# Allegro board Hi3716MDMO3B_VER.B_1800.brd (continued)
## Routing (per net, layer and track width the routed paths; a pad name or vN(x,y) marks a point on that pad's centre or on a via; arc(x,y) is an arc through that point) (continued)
VCC_SCI: length 16.9
  TOP w0.508: C193.1 R221.1 ; C193.1 257.34,82.94 256.73,82.33 J1.1 ; C193.1 C191.1 R130.2 258.71,86.65 C205.1 258.96,89.67 R274.2
VCC_SMT: length 11.8
  TOP w0.305: J26.1 221.66,50.95 220.67,51.94 J2.1 C223.1
VDD_AUDIO: length 19.1
  TOP w0.356: C75.1 208.67,129.07 209.18,128.56 U9.9
  TOP w0.381: v1(205.4,129.17) 205.51,129.06 R190.2 207.18,129.07 C75.1 ; C203.1 199.69,131.45 201.08,131.45 v1(203.36,129.17)
  TOP w0.508: C203.1 197.41,133.74 R151.2
  BOTTOM w0.381: v1(203.36,129.17) v1(205.4,129.17)
AUDIO_L: length 20.2
  TOP w0.254: R174.1 206.25,140.13 204.76,141.61 202.22,141.61 200.44,139.84 200.44,139.23 C216.1 197.24,136.69 196.12,137.8 196.12,139.43 J32.8
AUDIO_OUTL: length 28.1
  TOP w0.203: 205.07,101.81 204.45,102.43 U15.104
  TOP w0.254: 205.07,101.81 207.22,101.81 217.21,111.79 217.21,116.9 R152.1 C234.1
AUDIO_OUTR: length 26.2
  TOP w0.203: U15.105 204.76,102.83
  TOP w0.254: 204.76,102.83 206.74,102.83 215.94,112.02 215.94,116.96 R153.1 214.28,118.62 C235.2
AUDIO_R: length 4.6
  TOP w0.254: R175.2 C217.1 J32.7
CLK_50M_PHY0: length 90.7
  TOP w0.127: U3.9 103.45,115.74 102.78,115.07 102.78,109.86 105.9,106.74 134.19,106.74 138.78,111.34 177.89,111.34 178.85,110.37 179.33,110.37 C59.1 R162.2
CLK_50M_PHY1: length 79
  TOP w0.127: R163.2 C69.1 182.14,111.62 182.34,111.83 182.34,112.6 180.35,114.59 137.22,114.59 132.62,109.99 121.83,109.99 120.81,111.01 120.81,117.35 121.82,118.35 124.14,118.35 125.09,117.39 U4.9
CLK_SCI_NB: length 13.1
  TOP w0.305: J26.3 225.04,47.35 223.49,47.35 222.85,47.98 222.85,55.73 J2.2
CVBS: length 34.4
  TOP w0.203: U15.98 202.51,100.03 204.75,100.03
  TOP w0.254: 204.75,100.03 206.92,100.03 216.11,109.23 220.25,109.23 223.68,112.66 R34.2 R33.2 C70.1 223.68,117.74 224.21,118.26 U12.3
CVBS_OUT: length 21.3
  TOP w0.254: R65.1 220.03,131.58 216.7,131.58 214.79,133.49 C42.1 D3.3 J32.5
DATA_SCI_NB: length 46.7
  TOP w0.305: J26.7 230.67,14.88 J2.5
DDR_ADDR0: length 2.2
  TOP w0.127: U15.172 175.51,100.43 175.27,100.67 RN2.8
DDR_ADDR0_A: length 22.7
  TOP w0.127: U7.N3 160.81,91.03 160.81,91.61 160.53,91.89 160.23,91.89 159.98,92.13 159.98,93.49 160.18,93.68 160.18,96.91 164.6,101.33 172.57,101.33 173.23,100.67 RN2.1
DDR_ADDR1: length 5.8
  TOP w0.127: U15.17 185.42,76.81 R14.1
DDR_ADDR1_A: length 40.2
  TOP w0.127: U7.P7 159.9,87.94 158.22,87.94 156.55,86.27 156.55,81.67 163.76,74.46 173.57,74.46 174.46,73.57 182.18,73.57 R14.2
DDR_ADDR2: length 2.9
  TOP w0.127: R12.1 174.76,104.35 175.88,103.23 U15.165
DDR_ADDR2_A: length 32.2
  TOP w0.127: U7.P3 159.98,90.26 157.11,90.26 156.34,91.02 156.34,98.49 162.85,104.99 173.01,104.99 R12.2
DDR_ADDR3: length 2.2
  TOP w0.127: U15.173 175.35,100.03 175.22,100.16 RN2.7
DDR_ADDR3_A: length 19.8
  TOP w0.127: RN2.2 173.11,100.16 172.78,100.49 164.98,100.49 161.04,96.56 161.04,93.38 160.78,93.12 160.78,92.02 161.18,91.62 U7.N2
DDR_ADDR4: length 2.6
  TOP w0.127: RN5.8 182.62,78.64 U15.10
DDR_ADDR4_A: length 29.1
  TOP w0.127: U7.P8 159.98,86.26 159.98,84.9 159.77,84.69 159.77,82.44 164.86,77.35 174.79,77.35 175.68,76.46 180.44,76.46 RN5.1
DDR_ADDR5: length 2.4
  TOP w0.127: RN1.5 175.09,101.56 175.82,100.83 U15.171
DDR_ADDR5_A: length 22.7
  TOP w0.127: U7.P2 160.16,91.46 159.74,91.89 159.39,91.89 159.18,92.09 159.18,93.22 159.8,93.84 159.8,97.14 164.37,101.71 172.7,101.71 172.85,101.56 RN1.4
DDR_ADDR6: length 3.2
  TOP w0.127: RN5.7 183.17,78.47 183.17,79.52 183.42,79.77 U15.12
DDR_ADDR6_A: length 30.1
  TOP w0.127: U7.R8 159.18,86.26 159.18,82.49 164.7,76.97 174.64,76.97 175.52,76.08 180.78,76.08 RN5.2
DDR_ADDR7: length 2.5
  TOP w0.127: RN1.6 175.06,102.07 175.9,101.23 U15.170
DDR_ADDR7_A: length 24.2
  TOP w0.127: RN1.3 173.23,102.07 172.75,102.55 163.99,102.55 158.93,97.49 158.93,94.5 158.32,93.89 158.32,92.14 158.63,91.83 159.06,91.83 159.43,91.46 U7.R2
DDR_ADDR8: length 3.7
  TOP w0.127: RN5.6 183.68,78.26 183.68,79.26 184.22,79.8 U15.14
DDR_ADDR8_A: length 32.2
  TOP w0.127: RN5.3 180.99,75.57 180,75.57 179.67,75.24 175.12,75.24 174.23,76.13 164.36,76.13 158.21,82.28 158.21,86.09 U7.T8
DDR_ADDR9: length 2.4
  TOP w0.127: RN1.8 175.09,103.08 175.74,102.43 U15.167
DDR_ADDR9_A: length 27.6
  TOP w0.127: RN1.1 173.36,103.08 172.68,103.77 163.4,103.77 157.56,97.93 157.56,91.58 158.11,91.03 159.21,91.03 U7.R3
DDR_ADDR10: length 4
  TOP w0.127: U15.7 181.42,79.41 179.86,77.86 RN4.7
DDR_ADDR10_A: length 22.8
  TOP w0.127: RN4.2 177.46,77.86 175.89,79.42 165.73,79.42 162.41,82.75 162.41,87.09 U7.L7
DDR_ADDR11: length 4.1
  TOP w0.127: RN5.5 184.18,78.04 184.18,79 184.62,79.43 U15.15
DDR_ADDR11_A: length 34.8
  TOP w0.127: U7.R7 159.2,87.08 158.63,87.08 157.83,86.28 157.83,82.12 164.2,75.75 174.05,75.75 174.94,74.86 179.96,74.86 180.32,75.22 181.35,75.22 RN5.4
DDR_ADDR12: length 5.3
  TOP w0.127: U15.9 182.22,79.22 179.84,76.84 RN4.5
DDR_ADDR12_A: length 24.9
  TOP w0.127: RN4.4 176.67,76.84 175.32,78.19 165.21,78.19 160.78,82.62 160.78,87.06 U7.N7
DDR_ADDR13: length 5
  TOP w0.127: R13.1 172.78,104.35 173.49,103.64 175.01,103.64 175.82,102.83 U15.166
DDR_ADDR13_A: length 25.8
  TOP w0.127: U7.T3 157.92,90.66 157.18,91.4 157.18,98.1 163.23,104.15 171.53,104.15 R13.2
DDR_ADDR14: length 8.2
  TOP w0.127: U15.16 185.02,77.29 182.6,74.88 182.6,74.49 182.18,74.08 R15.1
DDR_ADDR14_A: length 33.9
  TOP w0.127: U7.T7 158.37,87.46 156.93,86.01 156.93,81.84 163.85,74.91 173.67,74.91 174.56,74.02 180.94,74.02 R15.2
DDR_BA0: length 2.5
  TOP w0.127: RN2.6 175.09,99.65 175.91,98.83 U15.176
DDR_BA0_A: length 19.1
  TOP w0.127: RN2.3 173.11,99.65 172.65,100.11 165.21,100.11 161.45,96.35 161.45,93.37 161.58,93.23 161.58,91.85 161.97,91.46 U7.M2
DDR_BA1: length 4.6
  TOP w0.127: U15.8 181.82,79.35 179.82,77.35 RN4.6
DDR_BA1_A: length 23.4
  TOP w0.127: RN4.3 176.69,77.35 175.47,78.57 165.36,78.57 161.4,82.53 161.4,84.67 161.58,84.85 161.58,86.26 U7.N8
DDR_BA2: length 2.4
  TOP w0.127: U15.177 175.78,98.43 175.06,99.15 RN2.5
DDR_BA2_A: length 18.4
  TOP w0.127: RN2.4 172.98,99.15 172.85,99.27 165.61,99.27 162.31,95.97 162.31,93.68 162.39,93.61 162.39,91.3 161.98,90.89 U7.M3
DDR_CASN: length 2.3
  TOP w0.127: U15.181 175.9,96.83 175.49,97.24 RN3.6
DDR_CASN_A: length 14.9
  TOP w0.127: U7.K3 163.58,90.85 164.01,91.27 164.01,92.46 164.4,92.85 164.4,94.96 166.66,97.22 173.34,97.22 173.36,97.24 RN3.3
DDR_CKE: length 5.1
  TOP w0.127: RN4.8 179.78,78.37 180.62,79.21 v1(180.62,79.26) 180.67,79.26 181.02,79.61 U15.6
  BOTTOM w0.127: v1(180.62,79.26) 181.26,79.26 181.64,79.64 R119.1
DDR_CKE_A: length 20.7
  TOP w0.127: RN4.1 177.51,78.37 176.07,79.8 165.88,79.8 162.8,82.89 162.8,85.08 U7.K9
DDR_CKN1: length 24.4
  TOP w0.165: U7.K7 163.58,87.22 163.98,86.82 163.98,85.52 164.25,85.25 164.25,83.55 R243.2 164.29,83.05 164.29,82.63 166.26,80.66 176.47,80.66 178.31,78.83 179.62,78.83 180.16,79.37 180.16,79.66 180.22,79.71 U15.4
DDR_CKP1: length 23.4
  TOP w0.165: U7.J7 164.38,87.4 164.79,86.99 164.79,85.52 164.54,85.27 164.54,83.61 R243.1 164.58,83.07 164.58,82.75 166.38,80.95 176.59,80.95 178.43,79.12 179.5,79.12 179.87,79.49 179.87,79.66 179.82,79.71 U15.3
DDR_CS0N_A: length 2.1
  TOP w0.127: U7.L2 162.78,91.26 162.38,90.85 v1(162.38,90.26)
  BOTTOM w0.127: R184.1 v1(162.38,90.26)
DDR_DM0: length 11.8
  TOP w0.127: U15.210 176.06,85.23 175.33,84.5 169.11,84.5 168.78,84.83 168.78,85.99 168.5,86.27 168.23,86.27 167.98,86.52 167.98,86.87 167.58,87.27 U7.E7
DDR_DM1: length 11
  TOP w0.127: U15.191 175.87,92.83 175.63,93.06 171.22,93.06 170.98,93.3 169.02,93.3 168.78,93.06 168.78,91.06 U7.D3
DDR_DQ0: length 11.9
  TOP w0.127: U15.189 175.77,93.63 175.71,93.57 171.24,93.57 171,93.81 168.73,93.81 167.98,93.06 167.98,91.32 167.58,90.92 U7.E3
DDR_DQ1: length 12.8
  TOP w0.127: U15.211 176.12,84.83 175.28,83.99 168.98,83.99 167.98,84.99 167.98,86.01 167.76,86.23 167.43,86.23 167.18,86.48 167.18,86.8 166.78,87.2 U7.F7
DDR_DQ2: length 12.9
  TOP w0.127: U15.188 175.89,94.03 175.51,94.41 171.6,94.41 171.36,94.65 167.98,94.65 167.18,93.86 167.18,91.86 U7.F2
DDR_DQ3: length 12.9
  TOP w0.127: U7.F8 166.78,86.4 167.18,86 167.18,84.62 168.65,83.16 175.06,83.16 175.93,84.03 U15.213
DDR_DQ4: length 16.1
  TOP w0.127: U7.H3 165.58,91.06 165.58,94.29 167.29,96 172.81,96 173.05,95.75 175.22,95.75 175.74,95.23 U15.185
DDR_DQ5: length 15.3
  TOP w0.127: U15.216 176.73,82.78 176.41,82.78 175.44,81.81 168.04,81.81 165.58,84.26 165.58,86.26 U7.H8
DDR_DQ6: length 13.7
  TOP w0.127: U15.186 175.66,94.83 175.57,94.92 172.67,94.92 172.43,95.16 167.79,95.16 166.38,93.76 166.38,91.86 U7.G2
DDR_DQ7: length 15.3
  TOP w0.127: U15.214 176.01,83.63 175.03,82.65 168.5,82.65 166.38,84.76 166.38,86.82 166.15,87.06 165.58,87.06 U7.H7
DDR_DQ8: length 9.1
  TOP w0.127: U7.D7 168.76,87.08 171.6,87.08 172,86.69 174.85,86.69 175.4,87.23 U15.205
DDR_DQ9: length 8.1
  TOP w0.127: U15.196 175.89,90.83 175.43,90.37 171.46,90.37 171.34,90.26 169.59,90.26 U7.C3
DDR_DQ10: length 8.9
  TOP w0.127: U7.C8 169.44,86.66 169.84,86.26 170.22,86.26 170.41,86.07 170.41,85.54 170.61,85.34 174.95,85.34 175.64,86.03 U15.208
DDR_DQ11: length 8.1
  TOP w0.127: U7.C2 169.58,91.86 171,91.86 171.37,92.22 175.38,92.22 175.58,92.43 U15.192
DDR_DQ12: length 6.4
  TOP w0.127: U7.A7 171.84,87.46 172.1,87.2 174.88,87.2 175.31,87.63 U15.204
DDR_DQ13: length 6.4
  TOP w0.127: U7.A2 171.11,91.46 171.37,91.72 175.46,91.72 175.77,92.03 U15.193
DDR_DQ14: length 7.5
  TOP w0.127: U7.B8 170.23,86.66 170.66,86.23 171.62,86.23 172.01,85.85 175.03,85.85 175.55,86.37 176,86.37 176.06,86.43 U15.207
DDR_DQ15: length 6.4
  TOP w0.127: U15.195 175.71,91.23 175.36,90.88 171,90.88 U7.A3
DDR_DQSN0: length 11.9
  TOP w0.165: U15.199 176.91,89.63 175.83,89.63 175.77,89.68 174.29,89.68 173.83,89.22 167.14,89.22 166.24,90.12 166.24,90.41 U7.G3
DDR_DQSN1: length 8
  TOP w0.165: U15.202 175.9,88.43 175.84,88.49 174.92,88.49 174.48,88.05 169.95,88.05 169.74,87.85 169.74,87.67 169.96,87.46 U7.B7
DDR_DQSP0: length 11.4
  TOP w0.165: U7.F3 166.53,90.41 166.53,90.24 167.26,89.51 173.71,89.51 174.17,89.97 175.77,89.97 175.83,90.03 176.91,90.03 U15.198
DDR_DQSP1: length 8.4
  TOP w0.165: U7.C7 169.45,87.73 169.45,87.97 169.83,88.34 174.36,88.34 174.8,88.78 175.85,88.78 175.9,88.83 176.73,88.83 U15.201
DDR_ODT: length 2.2
  TOP w0.127: RN3.7 175.3,97.75 175.42,97.63 U15.179
DDR_ODT_A: length 14.5
  TOP w0.127: RN3.2 173.11,97.75 172.8,98.05 166.27,98.05 163.54,95.32 163.54,92.58 163.58,92.54 U7.K1
DDR_RASN: length 2.3
  TOP w0.127: RN3.5 175.47,96.73 175.78,96.43 U15.182
DDR_RASN_A: length 14.1
  TOP w0.127: U7.J3 164.38,90.83 164.78,91.23 164.78,92.59 164.73,92.65 164.73,94.68 166.88,96.83 173.23,96.83 173.34,96.73 RN3.4
DDR_RSTN: length 2.4
  TOP w0.127: RN1.7 175.06,102.57 175.61,102.03 U15.168
DDR_RSTN_A: length 26.8
  TOP w0.127: U7.T2 158.39,91.46 v2(158.15,91.7) 157.94,91.91 157.94,94.04 158.43,94.52 158.43,97.57 163.79,102.93 172.88,102.93 173.23,102.57 RN1.2
  BOTTOM w0.127: v2(158.15,91.7) 158.15,91.58 158.84,90.9 R183.2 C65.1
DDR_VREF_CA: length 4.3
  TOP w0.305: U7.M8 161.97,86.66 v1(161.58,87.06)
  BOTTOM w0.381: v1(161.58,87.06) 160.97,87.06 C137.1 R225.2 R224.1 C136.2
DDR_VREF_DQ: length 5
  TOP w0.305: U7.H1 v1(165.18,92.9)
  BOTTOM w0.381: R227.1 C146.2 165.14,95.37 R226.2 C145.1 164.48,93.6 v1(165.18,92.9)
DDR_WEN: length 2.2
  TOP w0.127: U15.178 175.47,98.03 175.24,98.26 RN3.8
DDR_WEN_A: length 16.9
  TOP w0.127: U7.L3 162.78,90.88 163.16,91.26 163.16,95.55 166.05,98.43 173.06,98.43 173.23,98.26 RN3.1
DETECT_SCI_NB: length 11
  TOP w0.305: J2.6 234.92,54.29 234.92,48.34 J26.17
DM_USB0: length 76.7
  TOP w0.203: J12.2 146.62,138.23 142.76,138.23 D7.1 142,138.26 141.59,138.26 141.21,137.88 141.21,135.32 143.93,132.6 157,132.6 167.26,122.34 183.27,122.34 191.55,114.06 191.55,107.48 191.42,107.35 U15.131
DM_USB1: length 53.2
  TOP w0.203: U15.136 189.42,107.71 189.77,108.07 189.77,114.25 184.5,119.52 158.29,119.52 D9.1 157.15,119.44 151.11,119.44 150.52,120.03 150.52,121.23 J19.2
DP_USB0: length 76.1
  TOP w0.203: J12.3 146.62,137.88 142.71,137.88 D8.1 142,137.9 141.74,137.9 141.57,137.73 141.57,135.47 144.08,132.96 157.15,132.96 167.41,122.69 183.42,122.69 191.9,114.21 191.9,107.27 191.82,107.19 191.82,106.14 U15.130
DP_USB1: length 52.7
  TOP w0.203: U15.137 189.02,107.82 189.41,108.21 189.41,114.1 184.35,119.16 157.84,119.16 D10.1 150.96,119.09 150.17,119.88 150.17,121.29 J19.3
ETH_RSTN: length 115.5
  TOP w0.127: U15.164 175.89,103.63 175.39,104.12 175.39,104.71 v1(175.67,104.99) ; v1(175.55,109.98) 139.28,109.98 134.8,105.5 121.27,105.5 120.94,105.17 120.18,105.17 v1(120.05,105.29) v1(116.62,105.29) ; v1(130.91,117.92) 130.91,117.7 130.6,117.39 U4.32 ; v1(111.8,116.47) 111.8,116.04 111.5,115.74 U3.32 ; v1(115.35,113.93) 115.35,110.88 v1(116.62,109.61) ; v1(125.89,119.01) 125.06,119.85 120.25,119.85 119.8,119.39 119.8,109.86 120.05,109.61 v1(120.05,109.64)
  BOTTOM w0.127: C153.1 R120.1 130.99,117.99 v1(130.91,117.92) 130.91,117.68 130.72,117.48 126.53,117.48 126.02,117.99 126.02,118.88 v1(125.89,119.01) ; v1(175.55,109.98) 174.92,109.34 174.92,107.96 175.67,107.2 v1(175.67,104.99) ; v1(120.05,109.64) v1(120.05,105.29) ; v1(115.35,113.93) 114.59,114.69 112.05,114.69 111.8,114.94 v1(111.8,116.47) ; v1(116.62,105.29) v1(116.62,109.61)
FP_CLK: length 36.7
  TOP w0.127: R96.2 161.18,71.34 171.99,71.34 173.22,70.11 183.45,70.11 188.34,74.99 188.34,79.79 188.22,79.91 U15.24
FP_CLK_NB: length 98
  TOP w0.127: R66.1 U8.3 99.86,17.15 100.65,16.36 103.16,16.36 109.16,22.36 152.98,22.36 156.37,25.76 156.37,28.62 155.26,29.73 145.99,29.73 144.69,31.03 144.69,34.58 143.2,36.08 140.5,36.08 139.13,37.44 J28.4 J15.4
FP_IO: length 40
  TOP w0.127: U15.22 187.42,79.96 188.06,79.32 188.06,75.18 183.29,70.41 173.34,70.41 172.11,71.65 160.96,71.65 160.44,71.13 157.41,71.13 R95.2
FP_IO_NB: length 96.9
  TOP w0.127: J15.3 J28.3 137.13,38.3 139.74,35.7 143.04,35.7 144.31,34.43 144.31,30.87 145.83,29.35 155.1,29.35 155.99,28.46 155.99,25.92 152.82,22.74 109,22.74 103,16.74 101.67,16.74 101.13,17.28 U8.2 R60.1
FP_IR_NB: length 41.3
  TOP w0.127: R71.1 151.06,16.01 D4.1 158.02,19.19 158.02,33.31 J28.10 J15.10
FP_STB: length 33.3
  TOP w0.127: R101.2 164.55,71.03 171.84,71.03 173.08,69.79 183.57,69.79 188.62,74.84 U15.25
FP_STB_NB: length 98.7
  TOP w0.127: J15.5 J28.5 141.13,37.35 142.02,36.46 143.35,36.46 145.07,34.74 145.07,31.19 146.15,30.11 155.42,30.11 156.75,28.77 156.75,25.6 153.13,21.98 109.32,21.98 103.32,15.98 99.51,15.98 98.59,16.9 U8.4 R67.1
FUNC_SEL: length 2.2
  TOP w0.127: U15.21 187.02,79.73 187.54,79.21 R118.1
HDMI_REXT: length 3.1
  TOP w0.127: U15.116 v1(197.42,104.86)
  BOTTOM w0.127: v1(197.42,104.86) 197.5,104.94 R121.1 198.5,105.62 R277.1
IF_AGC: length 2.8
  TOP w0.127: R218.2 204.02,94.34 203.93,94.43 U15.84
IR_IN: length 25.8
  TOP w0.127: R107.2 175.19,66.43 182.66,66.43 191.02,74.79 U15.31
JTAG_SEL: length 4.2
  TOP w0.127: v1(178.88,109.1) 179.11,108.87 179.11,107.83 179.42,107.52 U15.161
  BOTTOM w0.127: R117.1 178.88,108.98 v1(178.88,109.1)
KEY_INT: length 25.2
  TOP w0.127: U15.30 190.62,74.82 182.51,66.71 175.17,66.71 R105.2
KEY_INT_NB: length 169.8
  TOP w0.381: 109.64,19.36 S10.2 118.23,21.47 153.45,21.47 157.39,25.41 157.39,28.9 S4.2 S4.1 147.73,33.92 149.13,35.32 J28.9 J15.9 ; 109.64,19.36 S10.1 ; 109.64,19.36 105.78,15.5 98.08,15.5 97.32,16.27 U8.5 R68.2 ; S9.1 S9.2 122.33,38.56 S7.1 ; S7.1 S7.2 S6.1 S6.2 ; S7.1 S5.2 S5.1 S8.2 S8.1
  BOTTOM w0.381: S6.2 S4.1
LED0_BASE: length 41.1
  TOP w0.127: R51.2 115.22,117.62 115.22,125.24 114.08,126.37 97.45,126.37 95.54,128.28 95.54,136.48 J23.9
LED0_LINK_ACT: length 29.9
  TOP w0.127: J23.11 110.53,137.42 114.34,137.42 117,134.76 117,126.63 115.5,125.12 115.5,116.5 R52.2
LED1_BASE: length 35.5
  TOP w0.127: R54.2 133.33,120.08 131.86,121.55 131.86,126.37 130.85,127.39 118.91,127.39 v1(118.15,128.15)
  BOTTOM w0.127: v1(118.15,128.15) 118.15,133.94 J24.9
LED1_LINK_ACT: length 25.8
  TOP w0.127: J24.11 138.47,134.63 138.47,129.3 137.58,128.41 137.58,122.82 134.15,119.39 134.15,117.36 133.85,117.06 R53.2
LED_CLK: length 20.4
  TOP w0.127: R176.1 177.85,68.47 183.05,68.47 189.42,74.84 U15.27
LED_DATA: length 21.3
  TOP w0.127: U15.28 189.82,74.84 183.13,68.16 178.93,68.16 178.7,67.93 R98.1 R142.1
LED_STANDBY: length 22.5
  TOP w0.127: R103.2 175.42,69.1 175.84,69.51 183.69,69.51 189.02,74.84 U15.26
LED_STANDBY_NB: length 50.4
  TOP w0.127: J28.7 J15.7 147.42,46.24 159.29,46.24 172.27,33.26 R45.2
MDCK: length 101.5
  TOP w0.127: v1(121.96,111.52) 122.46,112.02 122.46,115.2 122.72,115.46 R164.1 ; R165.1 v1(104.28,111.64) ; v1(101.26,111.64) 101.26,109.86 105.32,105.8 120.69,105.8 v1(120.81,105.67) 120.94,105.8 134.66,105.8 139.28,110.42 176.95,110.42 R99.1 R141.1 177.18,109.13 178.97,107.34 U15.162
  BOTTOM w0.127: v1(121.96,111.52) 121.7,111.52 120.56,110.37 120.56,105.93 v1(120.81,105.67) ; v1(101.26,111.64) v1(104.28,111.64)
MDIO: length 114.4
  TOP w0.127: v1(121.96,112.28) 121.96,115.71 122.21,115.96 124.24,115.96 124.68,116.39 U4.11 ; U15.163 175.92,104.08 175.77,104.23 175.77,104.45 176.31,104.99 v1(176.41,104.99) ; U3.11 105.75,114.74 v1(105.62,114.61) ; v1(176.31,109.86) 175.98,109.53 139.28,109.53 134.94,105.19 121.47,105.19 121.07,104.78 v1(119.42,104.78) 105.83,104.78 100.49,110.12 v1(100.49,111.64)
  BOTTOM w0.127: v1(105.62,114.61) 105.32,114.31 105.32,113.29 104.18,112.15 101,112.15 v1(100.49,111.64) ; v1(119.42,104.78) 119.42,109.74 v1(121.96,112.28) ; R203.1 176.72,110.27 v1(176.31,109.86) 175.42,108.98 175.42,107.96 176.06,107.32 176.06,105.34 v1(176.41,104.99)
MUTE_CTL: length 26.5
  TOP w0.127: U15.106 204.6,103.23 205.27,103.9 206.41,103.9 212.51,109.99 212.51,114.94 209.36,118.09 R50.1
NF_ALE: length 16.5
  TOP w0.127: U15.64 206.52,86.43 211.85,81.1 U21.17
NF_CLE: length 16.5
  TOP w0.127: U21.16 211.86,81.6 206.63,86.83 U15.65
NF_CS0N: length 15.2
  TOP w0.127: U15.66 213.39,87.23 215.52,85.1 U21.9
NF_DQ0: length 38.2
  TOP w0.127: U21.29 235.32,79.6 232.95,77.24 215.67,77.24 214.64,78.27 211,78.27 204.04,85.23 U15.61
NF_DQ1: length 42
  TOP w0.127: U21.30 237.14,80.1 237.39,79.85 237.39,77.51 236.84,76.96 215.46,76.96 214.43,77.99 210.8,77.99 204.36,84.43 U15.59
NF_DQ2: length 43.1
  TOP w0.127: U21.31 237.32,80.6 237.67,80.25 237.67,77.36 236.99,76.68 215.21,76.68 214.18,77.71 210.61,77.71 204.29,84.03 U15.58
NF_DQ3: length 44.3
  TOP w0.127: U21.32 237.32,81.1 238.02,80.4 238.02,77.22 237.2,76.39 215,76.39 213.96,77.43 210.45,77.43 204.24,83.63 U15.57
NF_DQ4: length 50.3
  TOP w0.127: U21.41 238.29,85.6 238.8,85.1 238.8,77.56 237.35,76.11 214.77,76.11 213.75,77.13 210.3,77.13 204.2,83.23 U15.56
NF_DQ5: length 51.4
  TOP w0.127: U15.55 202.51,82.78 204.21,82.78 210.14,76.84 213.52,76.84 214.55,75.81 237.54,75.81 239.08,77.35 239.08,85.33 238.3,86.1 U21.42
NF_DQ6: length 54.4
  TOP w0.127: U21.43 238.31,86.6 239.38,85.53 239.38,77.12 237.78,75.52 214.34,75.52 213.32,76.54 205.44,76.54 202.41,79.57 200.51,79.57 200.27,79.81 U15.54
NF_DQ7: length 56.1
  TOP w0.127: U15.53 199.82,79.83 200.42,79.23 202.26,79.23 205.23,76.26 213.09,76.26 214.11,75.24 238.03,75.24 239.66,76.87 239.66,85.76 238.31,87.1 U21.44
NF_RDY0: length 15.1
  TOP w0.127: U21.7 215.43,86.1 213.51,88.03 U15.68
NF_REN: length 15.2
  TOP w0.127: U15.67 213.4,87.63 215.42,85.6 U21.8
NF_WEN: length 16.4
  TOP w0.127: U21.18 211.84,80.6 206.82,85.63 U15.62
NF_WP: length 3.4
  TOP w0.127: U21.19 215.76,80.1 215.55,79.9 R102.1 R208.2
P_GND: length 80.5
  TOP w0.381: v1(13.88,92.59) 13.71,92.76 R4.2 ; v1(24.51,95.05) 24.64,95.18 R239.2 ; v1(30.77,122.69) C194.1 30.11,121.95 ; v1(28.61,74.05) C197.2 ; C29.2 v1(20.23,98.56) ; R82.2 23.62,96.2 v1(23.49,96.07) ; C200.2 v1(28.32,96.07) ; C198.2 v1(30.64,85.73) ; R3.2 v1(12.19,76.12) ; C63.2 v1(26.29,73.07) ; C30.2 v1(20.67,76.84) ; R83.2 v1(24.38,74.09) ; C64.2 v1(25.53,95.05) ; R238.2 v1(25.4,73.07)
  TOP w0.508: R242.1 v1(19.98,118.37)
  TOP w0.635: 30.41,114.23 C236.2 ; C236.2 31.49,112.96 ; C236.2 32.57,114.23 ; C236.2 31.49,115.5 ; 20.06,101.66 C269.2 ; C269.2 18.98,102.93 ; C269.2 20.06,104.2 ; C269.2 21.14,102.93 ; C270.2 20.55,80.53 ; C270.2 19.47,81.8 ; C270.2 19.47,79.26 ; C270.2 18.39,80.53 ; J22.8 12.24,70.84 ; J22.8 10.97,69.31 ; J22.8 12.24,67.79 ; J20.3 25.81,143.8 ; J20.3 24.15,141.13 ; J20.3 24.15,146.46 ; J20.3 22.5,143.8 ; J20.1 31.62,147 ; J20.1 28.95,145.35 ; J20.1 28.95,148.65 ; J20.1 26.29,147
  BOTTOM w0.635: J20.3 25.81,143.8 ; J20.3 24.15,141.13 ; J20.3 24.15,146.46 ; J20.3 22.5,143.8 ; 26.29,147 J20.1 ; J20.1 28.95,148.65 ; J20.1 31.62,147 ; J20.1 28.95,145.35 ; 30.41,114.23 C236.2 ; C236.2 31.49,115.5 ; C236.2 31.49,112.96 ; C236.2 32.57,114.23 ; J22.8 12.24,70.84 ; J22.8 10.97,69.31 ; J22.8 12.24,67.79 ; 30.77,87.45 C237.2 ; C237.2 29.5,88.53 ; C237.2 32.04,88.53 ; C237.2 30.77,89.61
  vias: v1(8,134.3) v1(8,131.76) v1(8,129.22) v1(8,126.68) v1(8,124.14) v1(8,121.6) v1(8,119.06) v1(8,116.52) v1(8,113.98) v1(8,111.44) v1(8,108.9) v1(8,106.36) v1(8,93.66) v1(8,91.12) v1(8,88.58) v1(8,81.34) v1(8,78.8) v1(8,76.26) v1(8,73.72) v1(8,71.18) v1(8.16,148.6) v1(8.13,83.12) v1(8.29,69.73) v1(8.42,55) v1(8.67,150) v1(8.67,95.13) v1(9.43,66.18) v1(9.43,63.64) v1(9.43,53.48) v1(9.52,140.27) v1(9.69,150.76) v1(10.54,139.38) v1(10.54,136.84) v1(10.54,134.3) v1(10.54,131.76) v1(10.54,129.22) v1(10.54,126.68) v1(10.54,124.14) v1(10.54,121.6) v1(10.54,119.06) v1(10.54,106.36) v1(10.54,73.72) v1(10.54,71.18) v1(10.54,68.64) v1(10.7,65.03) v1(11.72,150.89) v1(11.97,66.18) v1(11.97,63.64) v1(11.97,53.48) v1(12.86,105.04) v1(12.99,138.95) v1(13.08,136.84) v1(13.08,134.3) v1(13.08,131.76) v1(13.08,129.22) v1(13.08,126.68) v1(13.08,124.14) v1(13.08,121.6) v1(13.08,119.06) v1(13.08,73.72) v1(14.35,150.68) v1(14.39,140.98) v1(14.51,66.18) v1(14.51,53.48) v1(15.62,149.66) v1(15.62,139.38) v1(15.62,136.84) v1(15.62,134.3) v1(15.62,131.76) v1(15.62,129.22) v1(15.62,126.68) v1(15.62,124.14) v1(15.62,121.6) v1(15.62,119.06) v1(16.17,94.37) v1(16.17,92.72) v1(16.89,150.68) v1(17.05,66.18) v1(17.05,61.1) v1(17.05,58.56) v1(17.05,56.02) v1(17.05,53.48) v1(17.14,140.65) v1(17.78,147.1) v1(18.16,149.66) v1(18.71,94.37) v1(18.71,92.72) v1(19.43,150.68) v1(19.59,66.18) v1(19.59,63.64) v1(19.59,61.1) v1(19.59,58.56) v1(19.59,56.02) v1(19.59,53.48) v1(19.68,147.89) v1(19.94,140.65) v1(19.98,125.99) v1(19.98,123.45) v1(19.98,120.91) v1(19.98,107.07) v1(20.48,97.04) v1(20.7,149.66) v1(20.86,83.32) v1(20.86,80.78) v1(20.86,78.24) v1(21.25,94.37) v1(21.25,92.72) v1(21.46,146.11) v1(21.75,99.96) v1(21.75,96.66) v1(21.75,74.56) v1(21.97,150.68) v1(21.97,139.63) v1(22.01,76.34) v1(22.01,54.49) v1(22.13,66.18) v1(22.13,63.64) v1(22.13,61.1) v1(22.13,58.56) v1(22.13,56.02) v1(22.52,125.99) v1(22.52,123.45) v1(22.52,120.91) v1(22.52,118.37) v1(22.64,102.63) v1(22.77,104.53) v1(23.02,107.07) v1(23.15,98.82) v1(23.24,149.66) v1(23.4,83.32) v1(23.4,80.78) v1(23.4,78.24) v1(23.79,94.37) v1(23.79,92.72) v1(24.13,147.76) v1(24.51,150.68) v1(24.55,54.49) v1(24.67,103.51) v1(24.67,101.74) v1(24.67,66.18) v1(24.67,63.64) v1(24.67,61.1) v1(24.67,58.56) v1(24.67,56.02) v1(25.44,81.42) v1(25.44,79.64) v1(25.78,149.66) v1(25.94,102.63) v1(26.33,94.37) v1(26.33,92.72) v1(26.41,96.07) v1(26.58,80.53) v1(27.05,150.68) v1(27.09,54.49) v1(27.21,103.51) v1(27.21,101.74) v1(27.21,66.18) v1(27.21,61.1) v1(27.21,58.56) v1(27.21,56.02) v1(27.6,123.45) v1(27.6,120.91) v1(27.6,118.37) v1(27.85,81.42) v1(27.85,79.64) v1(27.98,92.85) v1(28.32,149.66) v1(28.74,99.7) v1(28.87,104.4) v1(28.87,101.86) v1(28.87,94.37) v1(29.37,122.06) v1(29.59,150.68) v1(29.75,66.18) v1(29.75,63.64) v1(30.01,82.05) v1(30.01,79.51) v1(30.01,76.97) v1(30.01,74.43) v1(30.14,98.56) v1(30.14,96.66) v1(30.52,53.73) v1(30.86,149.66) v1(30.9,112.02) v1(30.99,143.82) v1(31.15,105.29) v1(31.15,102.75) v1(31.15,100.21) v1(31.28,107.83) v1(32.13,150.68) v1(32.29,96.66) v1(32.29,66.18) v1(32.29,63.64) v1(32.29,53.48) v1(32.55,111.64) v1(32.55,109.1) v1(32.55,106.56) v1(32.55,104.02) v1(32.55,101.48) v1(32.55,98.94) v1(32.76,147.38) v1(33.4,149.66) v1(34.67,150.68) v1(34.67,148.39) v1(34.67,145.85) v1(34.67,143.31) v1(34.67,138.74) v1(34.67,136.2) v1(34.67,133.66) v1(34.67,131.12) v1(34.67,128.58) v1(34.67,126.04) v1(34.83,66.18) v1(34.83,63.64) v1(34.83,53.48) v1(35.94,149.66) v1(35.94,147.12) v1(35.98,125.1) v1(35.98,68.08) v1(36.1,128.53) v1(36.1,77.23) v1(36.1,74.69) v1(36.1,72.15) v1(36.23,121.17) v1(36.23,118.63) v1(36.23,116.09) v1(36.23,113.55) v1(36.23,111.01) v1(36.23,108.47) v1(36.23,105.93) v1(36.23,103.39) v1(36.23,100.85) v1(36.23,98.31) v1(36.23,95.77) v1(36.23,93.23) v1(36.23,90.69) v1(36.23,79.77)
PB: length 35.6
  TOP w0.203: 203.67,97.63 202.51,97.63 U15.92
  TOP w0.254: U17.1 226.48,117.99 224.92,116.43 C284.1 R159.2 R157.2 224.92,112.12 220.97,108.16 216.65,108.16 206.36,97.88 204.24,97.88 204.04,97.68 203.72,97.68 203.67,97.63
PB_OUT: length 16.7
  TOP w0.254: R252.1 225.33,128.33 225.33,129.8 221.65,133.49 C54.1 D1.3 J32.4
PHY1_AD1: length 2.3
  TOP w0.127: U4.14 124.61,114.89 124.01,114.3 R212.1
PR: length 39.5
  TOP w0.203: 204.26,96.83 U15.90
  TOP w0.254: U17.3 229.02,117.22 229.49,116.75 C286.1 R160.2 R161.2 229.49,113.13 222.29,105.93 217.43,105.93 208.57,97.06 204.79,97.06 204.55,96.83 204.26,96.83 204.26,96.83
PR_OUT: length 12
  TOP w0.254: R251.1 229.39,130.06 C53.1 D2.3 231.29,136.97 231.62,137.3 J32.1
PWR_BUTTON: length 25
  TOP w0.127: R104.2 175.91,66.99 182.38,66.99 190.22,74.83 U15.29
PWR_BUTTON_NB: length 40.3
  TOP w0.127: J28.8 J15.8 148.41,45.22 151.67,45.22 158.53,38.36 158.53,29.46 S3.3 ; S3.3 S3.4 ; S3.3 160.44,27.55 R70.1
QAM_SCL: length 57.9
  TOP w0.127: R58.1 v1(238.67,113.67) 235.82,113.67 224.47,102.32 218.76,102.32 209.95,93.51 203.61,93.51 203.49,93.63 U15.82 ; v1(240.22,120.18) 241.11,120.18 241.46,120.53 241.46,123.2 R35.1
  BOTTOM w0.127: v1(240.22,120.18) 240.7,119.69 240.7,118.75 239.69,117.74 239.69,114.69 v1(238.67,113.67)
QAM_SDA: length 56.8
  TOP w0.127: v1(240.22,119.39) 240.5,119.67 241.23,119.67 241.84,120.28 241.84,123.45 R37.1 ; U15.83 203.97,94.03 204.21,93.79 209.81,93.79 218.65,102.63 224.37,102.63 236.48,114.74 v1(238.67,114.74) 238.74,114.82 R59.1
  BOTTOM w0.127: v1(240.22,119.39) 240.22,119.03 239.3,118.12 239.3,115.38 v1(238.67,114.74)
QAM_VINN: length 64
  TOP w0.165: C55.2 247.9,127.7 247.9,119.76 246.51,118.38 236.74,118.38 223.27,104.91 217.88,104.91 208.95,95.98 208.58,95.98 203.57,95.98 203.52,96.03 202.33,96.03 U15.88
QAM_VINP: length 64.5
  TOP w0.165: C52.2 248.58,128.11 248.19,127.73 248.19,119.64 246.64,118.08 236.86,118.08 223.39,104.62 218,104.62 209.07,95.69 208.7,95.69 203.58,95.69 203.52,95.63 202.33,95.63 U15.87
REXT_VDAC: length 3.8
  TOP w0.127: U15.95 203.83,98.83 204.2,98.46 R168.2 R230.2
RF_IN: length 3.4
  TOP w0.44: L6.2 C206.1 259.6,145.66 arc(259.46,146.33) J13.2
RF_OUT: length 2.3
  TOP w0.44: R27.1 J13.1
RST_SCI_NB: length 7.6
  TOP w0.305: J26.2 225.67,50.52 J2.3
RX+_PHY0: length 10.4
  TOP w0.165: T2.6 104.78,123.23 105.06,122.95 105.69,122.95 105.99,122.65 105.99,122.06 105.47,121.55 R21.2 105.47,121.24 106.05,120.67 106.05,119.93 108.72,117.26 108.72,117.08 108.62,116.97 U3.5
RX+_PHY1: length 9
  TOP w0.165: T1.6 126.62,124.24 126.9,123.96 127.53,123.96 127.83,123.66 127.83,123.36 127.32,122.85 R23.2 127.32,121.89 127.48,121.72 127.73,121.72 127.9,121.56 127.9,120.4 127.64,120.15 127.64,118.73 127.54,118.62 U4.5
RX-_PHY0: length 10.3
  TOP w0.165: T2.8 107.32,123.18 107.09,122.95 106.58,122.95 106.28,122.65 106.28,122.2 106.92,121.55 R22.2 106.92,121.24 106.34,120.67 106.34,120.05 109.01,117.38 109.01,117.08 109.12,116.97 U3.4
RX-_PHY1: length 8.9
  TOP w0.165: U4.4 128.04,118.62 127.93,118.73 127.93,120.02 128.19,120.28 128.19,121.56 128.35,121.72 128.6,121.72 128.77,121.89 R24.2 128.77,122.74 128.12,123.38 128.12,123.66 128.42,123.96 128.93,123.96 129.16,124.19 T1.8
RXD0_RMII0: length 82.6
  TOP w0.127: U15.158 180.62,106.96 180.43,107.15 180.43,111.52 179.41,112.53 138.25,112.53 133.67,107.95 107.23,107.95 106.58,108.6 R74.1
RXD0_RMII1: length 69.5
  TOP w0.127: U15.149 184.22,111.67 180.1,115.78 136.64,115.78 132.04,111.19 124.29,111.19 R77.1
RXD1_RMII0: length 83.1
  TOP w0.127: R75.1 105.69,108.6 106.62,107.67 133.8,107.67 138.37,112.24 179.27,112.24 180.12,111.39 180.12,107.04 180.22,106.94 U15.159
RXD1_RMII1: length 70.1
  TOP w0.127: U15.150 183.82,111.64 179.95,115.5 136.81,115.5 132.22,110.91 123.55,110.91 R78.1
RXDV_RMII0: length 80.1
  TOP w0.127: U15.157 181.02,107.01 180.71,107.32 180.71,111.64 179.54,112.81 138.06,112.81 133.48,108.23 110.22,108.23 R73.1
RXDV_RMII1: length 65.4
  TOP w0.127: U15.148 184.62,111.66 180.22,116.06 136.41,116.06 132.11,111.76 R76.1
SFC_CLK: length 24.4
  TOP w0.127: U16.6 217.23,70.22 212.38,75.07 204.38,75.07 201.01,78.43 200.25,78.43 199.02,79.67 U15.51
SFC_CS1N: length 17.4
  TOP w0.127: U15.46 197.02,79.86 204.12,72.76 U16.1
SFC_DIO: length 25.4
  TOP w0.127: U15.50 198.62,79.56 204.15,74.03 212.02,74.03 217.1,68.95 U16.5
SFC_DOI: length 21.1
  TOP w0.127: U15.48 197.82,79.52 203.92,73.42 211.74,73.42 212.12,73.04 212.12,71.77 211.84,71.49 U16.2
SFC_HOLDN_IO3: length 23.4
  TOP w0.127: U16.7 217.37,71.49 212.88,75.98 204.86,75.98 201.97,78.88 200.32,78.88 199.42,79.77 U15.52
SFC_WPN_IO2: length 22.8
  TOP w0.127: U16.3 211.95,70.22 212.75,71.02 212.75,72.87 211.87,73.75 204.02,73.75 198.22,79.55 U15.49
SIM0_CARD_I/O: length 13.9
  TOP w0.508: J1.5 258.35,76.08 258.35,79.51 258.99,80.15 Q11.3 260.61,80.25 C306.1 R221.2
SIM0_CLK: length 2.6
  TOP w0.127: R36.1 196.22,78.99 U15.44
SIM0_CLK_OUT: length 17.4
  TOP w0.127: v1(246.92,77.23) 250.86,77.23 253.47,79.83 J1.2 ; v1(244.26,77.23) 242.22,75.18 U23.8 241.49,73.93 241.34,73.77 R235.1
  BOTTOM w0.127: v1(244.26,77.23) v1(246.92,77.23)
SIM0_DATA: length 77.7
  TOP w0.127: U15.41 195.02,78.51 207.64,65.89 221.74,65.89 227.06,71.21 243.96,71.21 245.05,70.11 252.26,70.11 253.02,70.88 255.05,70.88 259.5,75.32 R32.1
SIM0_DET: length 61.6
  TOP w0.127: U15.40 194.62,78.48 207.49,65.61 221.97,65.61 227.29,70.93 243.7,70.93 245.12,69.5 R106.1
SIM0_PWREN: length 82.5
  TOP w0.127: U23.4 245.78,79.02 245.78,76.08 ; U23.4 246.29,79 246.29,78.24 246.67,77.86 249.46,77.86 249.84,78.23 U23.1 ; U23.4 246.03,82.05 245.64,82.43 241.59,82.43 240.7,81.54 240.7,76.46 238.16,73.92 R237.2 237.17,73.47 237.02,73.31 225.7,73.31 220.39,68.01 208.47,68.01 196.62,79.86 U15.45 ; 245.78,76.08 244.76,75.06 U23.10 ; 245.78,76.08 246.54,76.08 247.3,75.33 U23.12
SIM0_PWREN_CTL: length 20.2
  TOP w0.127: U23.3 247.3,83.44 254.93,91.07 257.08,91.07 257.59,90.56 R222.1
SIM0_RST: length 66
  TOP w0.127: U23.5 244.76,76.71 244.13,76.08 244.13,72.02 243.6,71.48 226.83,71.48 221.51,66.17 207.77,66.17 195.42,78.52 U15.42
SIM0_RST_OUT: length 17.3
  TOP w0.127: v1(247.56,76.72) 251.62,76.72 252.24,77.33 J1.3 ; v1(243.49,77.1) U23.6 243.5,79.27 243.5,81.04 243.27,81.26 R232.1 C308.1
  BOTTOM w0.127: v1(243.49,77.1) 243.87,76.72 v1(247.56,76.72)
SPDIF_OUT: length 45.9
  TOP w0.127: U15.109 200.27,107.38 v1(200.45,107.56) 201.2,108.32 201.2,119.26 185.07,135.4 U11.1
  BOTTOM w0.127: v1(200.45,107.56) 200.45,107.09 201.08,106.46 R182.1
STANDBY_PWROFF: length 118.3
  TOP w0.127: v1(140.12,75.07) 140.35,74.84 R115.1 142,74.84 142.53,74.3 158.43,74.3 R97.2 160.13,72.6 172.55,72.6 173.65,71.51 183.22,71.51 186.62,74.91 U15.20 ; v1(127.67,77.48) 126.02,75.83 120.31,75.83 119.42,76.72 119.42,101.48 122.21,104.28 R93.2
  BOTTOM w0.127: v1(127.67,77.48) 133.77,77.48 136.18,75.07 v1(140.12,75.07)
TCK_ICE_FP: length 51.4
  TOP w0.127: J27.6 59.35,81.71 59.35,94.94 J16.5 ; J30.18 82.85,81.67 R46.2 80.2,82.05 80.01,82.24 77.82,82.24 65.7,94.37 v1(65.7,98.05)
  BOTTOM w0.127: J16.5 64.01,99.61 65.57,98.05 v1(65.7,98.05)
TDI_ICE_FP: length 65
  TOP w0.127: J27.8 54.27,81.71 54.27,92.21 v1(60.11,98.05) ; v1(69.76,98.05) 72.61,98.05 J16.1 75.98,97.8 75.98,89.8 77.38,88.4 v1(77.38,85.1) ; J30.17 84.69,79.89 82.71,79.89 82.08,80.53 R114.1 80.2,80.63 79.67,81.16 77.51,81.16 v1(77.38,81.29)
  BOTTOM w0.127: v1(69.76,98.05) 68.87,97.16 61,97.16 v1(60.11,98.05) ; v1(77.38,85.1) v1(77.38,81.29)
TDO_ICE_FP: length 49.6
  TOP w0.127: J30.16 80.86,82.86 80.81,82.81 R110.1 80.2,83.22 80.05,83.37 77.33,83.37 68.49,92.21 68.49,98.31 67.19,99.61 J16.4 61.76,94.82 61.76,81.83 J27.4
TMDS_CEC: length 62.4
  TOP w0.127: J25.13 166.09,140.4 166.66,139.84 166.66,134.37 169.45,131.58 R69.2 U14.3 184.24,133.38 199.35,118.28 199.35,108.87 198.22,107.75 U15.114
TMDS_CLK_N: length 59.6
  TOP w0.203: U15.118 196.62,106.14 196.62,107.15 196.58,107.18 196.58,107.42 197.31,108.14 197.35,108.14 197.36,108.16
  TOP w0.254: 197.36,108.16 198.15,108.95 198.15,116.92 186.31,128.76 170.36,128.76 165.31,133.81 165.31,136.71 165.37,136.77 U2.5 U2.6 165.37,139.84 165.59,140.06 J25.12
TMDS_CLK_P: length 59.6
  TOP w0.203: 197.09,108.43 197.08,108.41 197.08,108.38 196.25,107.55 196.25,107.18 196.22,107.15 196.22,106.14 U15.119
  TOP w0.254: 197.09,108.43 197.77,109.11 197.77,116.77 186.15,128.38 170.2,128.38 164.93,133.66 164.93,136.71 164.87,136.77 U2.4 U2.7 164.87,139.72 164.59,140 J25.10
TMDS_D0_N: length 59.2
  TOP w0.203: U15.120 195.82,107.16 195.82,107.16 195.78,107.2 195.78,107.82 195.81,107.84 195.81,107.87
  TOP w0.254: 195.81,107.87 195.81,108.81 196.52,109.53 196.52,116.39 185.7,127.22 169.78,127.22 163.8,133.2 163.8,136.7 163.87,136.77 U2.2 U2.9 163.87,139.71 164.09,139.94 J25.9
TMDS_D0_P: length 59.2
  TOP w0.203: U15.121 195.42,107.17 195.45,107.21 195.45,107.84 195.43,107.87
  TOP w0.254: J25.7 163.09,139.97 163.37,139.7 U2.10 U2.1 163.37,136.77 163.42,136.72 163.42,133.04 169.62,126.83 185.54,126.83 196.14,116.23 196.14,109.69 195.43,108.97 195.43,107.87
TMDS_D1_N: length 59.2
  TOP w0.203: 194.6,107.97 194.58,107.96 194.58,107.6 194.62,107.57 194.62,106.14 U15.123
  TOP w0.254: 194.6,107.97 194.6,109.43 195.01,109.84 195.01,115.78 185.07,125.72 168.99,125.72 162.27,132.44 162.27,136.58 162.32,136.64 U5.5 U5.6 162.32,139.81 162.59,140.09 J25.6
TMDS_D1_P: length 59.1
  TOP w0.203: 194.21,107.97 194.21,107.57 194.22,107.57 194.22,106.14 U15.124
  TOP w0.254: J25.4 161.59,140.08 161.82,139.85 U5.7 U5.4 161.82,136.65 161.88,136.58 161.88,132.29 168.84,125.34 184.91,125.34 194.63,115.62 194.63,110 194.21,109.59 194.21,107.97
TMDS_D2_N: length 58.9
  TOP w0.203: U15.126 193.42,107.13 193.4,107.15 193.4,108.14
  TOP w0.254: J25.3 161.09,139.98 160.82,139.71 U5.9 U5.2 160.82,136.66 160.76,136.6 160.76,131.67 168.18,124.24 184.1,124.24 193.4,114.94 193.4,108.14
TMDS_D2_P: length 58.8
  TOP w0.203: 193.02,108.14 193.02,107.15 193.02,107.15 U15.127
  TOP w0.254: J25.1 160.09,139.93 160.32,139.7 U5.10 U5.1 160.32,136.65 160.38,136.6 160.38,131.51 168.02,123.86 183.94,123.86 193.02,114.78 193.02,108.14
TMDS_HOTPLUG: length 58.5
  TOP w0.127: J25.19 169.09,140.44 169.83,139.71 170.97,139.71 171.35,139.33 171.35,137.81 171.63,137.53 C25.1 ; C25.1 171.79,137.21 U14.4 ; C25.1 R6.1 173.38,135.21 174.14,134.45 184.44,134.45 200.26,118.63 200.26,108.28 199.82,107.84 U15.110
TMDS_SCL: length 60.7
  TOP w0.127: J25.15 167.09,134.44 168.07,133.46 R79.1 169.07,133.46 169.15,133.38 U14.1 169.89,134.19 170.08,134.38 172.49,134.38 173.08,133.79 184.25,133.79 199.65,118.39 199.65,108.67 198.62,107.64 U15.113
TMDS_SDA: length 58.2
  TOP w0.127: J25.16 167.59,139.03 168.56,138.07 R72.1 168.92,136.31 169.33,135.9 169.87,135.9 U14.6 169.89,134.95 170.08,134.76 172.88,134.76 173.52,134.12 184.36,134.12 199.96,118.52 199.96,108.49 199.02,107.55 U15.112
TMS_ICE_FP: length 57.6
  TOP w0.127: J30.15 84.69,83.83 80.33,83.83 R111.1 80.2,84.31 79.92,84.59 76.74,84.59 69.09,92.25 J16.3 67.98,100.72 63.66,100.72 56.81,93.86 56.81,81.71 J27.7
TRST_ICE_FP: length 95.6
  TOP w0.127: J27.9 50.45,80.52 51.6,81.67 51.6,90.43 59.73,98.56 60.87,98.56 63.41,101.1 70.14,101.1 J16.2 73,100.97 75.09,100.97 76.49,99.58 76.49,89.8 80.2,86.09 R80.2 81.82,85.1 82.59,85.86 84.66,85.86 J30.13 86.38,84.86 87.29,83.96 87.29,74.18 86.14,73.03 81.82,73.03 79.54,70.75 R47.1
TS_RESET: length 65.8
  TOP w0.127: 205.9,94.34 C51.1 207.4,94.34 207.76,94.7 209.43,94.7 218.37,103.64 223.94,103.64 236.76,116.47 R293.1 239.53,116.85 239.66,116.98 247.69,116.98 249.46,118.75 249.46,125.61 251.78,127.92 R28.2
TS_SCL: length 29.7
  TOP w0.127: R58.2 240.7,113.67 240.96,113.42 240.96,112.79 240.57,112.4 237.02,112.4 230.54,105.93 230.54,100.59 232.45,98.69 R62.2 C332.1 236.69,98.69 237.27,98.11 J34.2
TS_SDA: length 34.8
  TOP w0.127: R59.2 v1(241.21,114.82) ; J34.4 240.15,97.04 237.4,97.04 236.76,97.68 C331.1 R61.2 232.92,97.68 230.16,100.44 230.16,106.09 236.99,112.91 v1(240.45,112.91)
  BOTTOM w0.127: v1(240.45,112.91) 241.21,113.67 v1(241.21,114.82)
TSI0_CLK: length 50.5
  TOP w0.127: U15.80 203.49,92.83 203.58,92.92 211.06,92.92 213.4,95.26 240.7,95.26 241.78,94.18 C315.1 244.13,95.26 246.21,97.34 246.21,99.12 J34.7
TSI0_D0: length 66.9
  TOP w0.127: J34.17 255.23,99.53 256.2,98.56 256.2,97.04 255.98,96.82 C312.1 255.31,93.6 255.31,91.88 249.13,85.71 241.11,85.71 236.89,89.93 214.54,89.93 213.02,88.41 202.35,88.41 U15.69
TSI0_D1: length 63.7
  TOP w0.127: J34.18 255.23,96.7 254.58,96.06 C316.1 253.91,93.6 253.91,90.94 249,86.04 241.24,86.04 237.07,90.2 214.31,90.2 212.81,88.71 203.87,88.71 203.74,88.83 U15.70
TSI0_D2: length 64.5
  TOP w0.127: U15.72 202.33,89.63 212.47,89.63 214.03,91.2 237.65,91.2 241.84,87 248.58,87 252.51,90.94 252.51,93.6 C319.1 253.19,96.19 254.24,97.24 254.24,99.1 J34.15
TSI0_D3: length 60.7
  TOP w0.127: J34.16 253.23,97.12 251.79,95.68 C317.1 251.12,93.6 251.12,90.81 248.32,88.02 242.48,88.02 238.35,92.15 213.71,92.15 212.15,90.59 204.4,90.59 203.85,90.03 U15.73
TSI0_D4: length 62.2
  TOP w0.127: U15.74 203.62,90.43 204.05,90.86 211.97,90.86 213.56,92.45 238.46,92.45 242.51,88.4 248.19,88.4 249.72,89.93 249.72,93.6 C313.1 250.39,95.43 252.26,97.29 252.26,99.08 J34.13
TSI0_D5: length 59.1
  TOP w0.127: J34.14 249,95.88 C318.1 248.32,93.6 248.32,91.32 248.83,90.81 248.83,89.67 248.55,89.39 C80.1 R56.2 247.05,89.39 246.49,88.84 242.51,88.84 238.58,92.76 213.43,92.76 211.81,91.14 203.8,91.14 203.49,90.83 U15.75
TSI0_D6: length 58.4
  TOP w0.127: U15.76 203.31,91.23 203.51,91.43 211.65,91.43 213.96,93.74 239.05,93.74 242.61,90.18 R57.2 C150.1 245.12,91.04 245.53,91.45 246.54,91.45 246.92,91.83 246.92,93.6 C314.1 247.6,95.05 250.23,97.67 250.23,99.11 J34.11
TSI0_D7: length 53.2
  TOP w0.127: J34.12 246.2,95.09 C320.1 245.68,94.27 245.15,93.74 245.15,92.08 244.51,91.45 241.76,91.45 239.19,94.01 213.83,94.01 211.54,91.73 203.71,91.73 203.4,92.03 U15.78
TSI0_SYNC: length 44.9
  TOP w0.127: U15.81 203.24,93.23 203.24,93.22 210.09,93.22 213.14,96.28 243.39,96.28 J34.8
TSI0_VALID: length 64.1
  TOP w0.127: v1(245.4,94.88) 248.19,97.67 248.19,100.85 248.45,101.1 255.81,101.1 256.2,100.72 256.2,99.58 257.23,98.55 J34.20 ; U15.79 203.44,92.43 203.87,92.01 211.42,92.01 213.7,94.29 239.89,94.29 241.34,92.85 v1(242.98,92.85)
  BOTTOM w0.127: v1(245.4,94.88) 243.37,92.85 v1(242.98,92.85)
TX+_PHY0: length 15.9
  TOP w0.165: U3.7 107.62,116.97 107.72,117.08 107.72,117.24 105.82,119.14 100.23,119.14 99.45,119.92 99.45,120.72 98.87,121.3 R19.1 98.87,121.55 99.5,122.18 99.5,122.69 99.24,122.95 98.71,122.95 98.43,123.23 T2.1
TX+_PHY1: length 13.2
  TOP w0.165: T1.1 120.27,124.25 120.56,123.96 121.09,123.96 121.34,123.71 121.34,123.49 120.71,122.86 R17.1 120.71,121.89 120.88,121.72 121.13,121.72 121.29,121.56 121.29,121.17 121.69,120.77 125.45,120.77 126.64,119.58 126.64,118.73 126.54,118.62 U4.7
TX-_PHY0: length 16
  TOP w0.165: T2.3 100.97,123.18 100.74,122.95 100.04,122.95 99.79,122.69 99.79,122.08 100.32,121.55 R20.1 100.32,121.3 99.74,120.72 99.74,120.04 100.35,119.43 105.94,119.43 108.01,117.36 108.01,117.08 108.12,116.97 U3.6
TX-_PHY1: length 13.3
  TOP w0.165: U4.6 127.04,118.62 126.93,118.73 126.93,119.7 125.57,121.07 121.81,121.07 121.58,121.29 121.58,121.56 121.75,121.72 122,121.72 122.16,121.89 R18.1 122.16,122.86 121.63,123.39 121.63,123.71 121.89,123.96 122.56,123.96 122.81,124.22 T1.3
TXD0_RMII0: length 82.3
  TOP w0.127: U15.154 182.22,107.01 182.03,107.2 181.87,107.2 v1(181.52,107.55) 181.77,107.81 181.77,108.47 181.29,108.95 181.29,111.89 179.78,113.39 137.83,113.39 133.22,108.79 112.75,108.79 110.62,110.92 U3.24
  BOTTOM w0.127: v1(181.52,107.55) 181.42,107.45 R177.1
TXD0_RMII1: length 67.3
  TOP w0.127: U4.24 129.54,112.79 129.79,112.53 131.85,112.53 135.94,116.62 180.49,116.62 185.76,111.34 v1(185.76,110.63) 185.76,108.79 186.07,108.49 186.07,107.3 185.82,107.05 U15.145
  BOTTOM w0.127: v1(185.76,110.63) 185.46,110.32 R178.1
TXD1_RMII0: length 81.4
  TOP w0.127: U15.153 v1(182.62,107.48) 182.62,107.5 182.15,107.96 182.15,109.21 R143.1 181.87,109.23 181.6,109.51 181.6,111.99 179.91,113.67 137.7,113.67 133.11,109.08 115.12,109.08 111.96,112.24 U3.25
  BOTTOM w0.127: R100.1 v1(182.62,107.48)
TXD1_RMII1: length 65.1
  TOP w0.127: U15.144 186.22,106.94 186.35,107.07 186.35,108.61 186.57,108.84 R179.1 186.57,111.03 180.7,116.9 135.47,116.9 132.46,113.89 U4.25
TXEN_RMII0: length 81.9
  TOP w0.127: U3.23 110.12,110.78 112.39,108.51 133.36,108.51 137.96,113.12 179.64,113.12 181.01,111.75 181.01,108.6 v1(181.25,108.37) 181.01,108.13 181.01,107.43 181.42,107.02 U15.156
  BOTTOM w0.127: v1(181.25,108.37) R180.1
TXEN_RMII1: length 67.2
  TOP w0.127: U4.23 129.04,112.56 129.45,112.15 131.98,112.15 136.17,116.34 180.35,116.34 185.27,111.42 185.27,108.33 v1(185.58,108.02) 185.42,107.86 U15.146
  BOTTOM w0.127: R181.1 185.46,107.89 v1(185.58,108.02)
UART0_RXD: length 7.3
  TOP w0.127: U15.107 204.11,103.63 204.38,103.9 204.38,105.6 205.09,106.31 R124.1 Q8.3
UART0_TXD: length 9
  TOP w0.127: U15.108 203.57,104.08 203.77,104.28 R123.2 R122.2
USB_REXT: length 3.5
  TOP w0.203: U15.133 190.62,106.32 190.62,107.2 191.01,107.6 v1(191.01,107.66)
  BOTTOM w0.381: R91.2 191.01,109.33 v1(191.01,107.66)
VDAC_COMP: length 4.1
  TOP w0.203: v1(203.71,98.26) 203.54,98.43 U15.94
  BOTTOM w0.381: v1(203.71,98.26) 203.49,98.49 C89.2 202.83,97.87 C278.2
VREF_ADAC: length 4.4
  TOP w0.203: U15.102 201.47,101.63 v1(201.2,101.35)
  BOTTOM w0.381: v1(201.2,101.35) 201.81,101.96 C85.1 203.77,101.96 C277.1
XIN: length 11.5
  TOP w0.203: U15.36 193.02,78.05 194.45,76.62 R2.2 194.45,75.09 194.83,74.71 C260.1 194.55,74.02 194.55,73.54 X1.1
XOUT: length 5.6
  TOP w0.203: R11.2 192.97,75.4 R2.1 192.97,77.58 192.62,77.94 U15.35
Y: length 37.4
  TOP w0.203: 203.9,97.23 202.33,97.23 U15.91
  TOP w0.254: U17.2 227.75,117.48 227.2,116.94 C285.1 R156.2 R158.2 227.2,112.5 221.78,107.07 217.05,107.07 207.45,97.47 204.48,97.47 204.26,97.26 203.93,97.26 203.9,97.23
Y_OUT: length 14.1
  TOP w0.254: J32.2 224.11,139.43 D14.3 C56.1 226.99,131.45 227.36,131.08 R250.1
$4N8: length 4.8
  TOP w0.508: U10.1 139.6,89.67 140.59,90.66 R247.1 R7.1
$4N9: length 2.4
  TOP w0.381: v1(136.94,97.29) U19.1
  BOTTOM w0.381: C225.1 v1(136.94,97.29)
$4N10: length 0.9
  BOTTOM w0.381: C225.2 v1(139.48,97.29)
$4N25: length 5.3
  TOP w0.127: U19.7 138.21,105.17 137.83,105.55 135.93,105.55 134.68,104.3 R93.1
$4N89: length 3.5
  TOP w0.127: C250.1 139.98,106.41 C58.1 139.98,105.79 139.48,105.29 U19.6
$4N91: length 3
  TOP w0.127: C66.1 134.81,103.13 136.56,103.13 136.94,103.51 U19.8
$4N92: length 1
  TOP w0.127: C250.2 R228.1
$4N93: length 3.4
  TOP w0.381: U19.5 140.75,105.95 R81.2 R94.1
$4N348: length 4.2
  TOP w0.381: R55.1 R42.2 145.35,81.7 144.18,80.53 U18.1
$5N20: length 17.5
  TOP w0.127: Q3.1 R135.2 130.95,73.8 130.97,73.77 132.47,73.77 132.62,73.92 132.62,76.97 133.77,78.11 Q1.1 137.58,77.23 136.69,76.34 C4.1 R116.1
$5N64: length 2
  TOP w0.127: Q6.3 R116.2
$5N66: length 1.7
  TOP w0.127: R115.2 139.89,74.02 Q6.1
$6N108: length 2.3
  TOP w0.127: U15.160 179.82,107.63 179.61,107.83 R162.1
$6N109: length 4.3
  TOP w0.127: U15.151 183.42,108.46 183.5,108.54 183.5,109.59 R163.1
$6N160: length 5.2
  TOP w0.203: X1.2 194.09,73.29 194.09,74.08 C261.1 R11.1
$6N395: length 5.1
  TOP w0.127: R95.1 C201.1 155,66.52 J14.3
$6N397: length 5.7
  TOP w0.127: J14.4 156.91,67.35 158.56,69 C196.1 R96.1
$6N399: length 6.5
  TOP w0.127: R101.1 C176.1 162.11,69.63 J14.5
$6N401: length 13
  TOP w0.127: R103.1 C175.1 173.01,69.12 173.01,69.43 172.58,69.86 166.34,69.86 J14.7
$6N403: length 10.4
  TOP w0.127: R104.1 C174.1 173.04,68.44 172.88,68.59 167.07,68.59 J14.8
$6N405: length 8.1
  TOP w0.127: J14.9 168.18,67.7 169.84,67.7 169.96,67.57 172.91,67.57 173.04,67.45 C173.1 R105.1
$6N407: length 5.5
  TOP w0.127: J14.10 169.04,66.56 172.78,66.56 173.04,66.3 C172.1 R107.1
$7N340: length 2.5
  TOP w0.127: U15.99 203.64,100.43 203.74,100.53 v1(203.74,100.54)
  BOTTOM w0.127: R85.1 203.59,100.54 v1(203.74,100.54)
$7N342: length 4.4
  TOP w0.127: U15.100 203.35,100.83 203.52,101 204.1,101 204.51,100.59 v1(204.51,100.54)
  BOTTOM w0.127: R86.1 203.19,101.15 203.9,101.15 v1(204.51,100.54)
$10N107: length 2.8
  TOP w0.127: v1(162.4,87.89) 162.88,87.89 163.2,87.57 163.2,87.08 U7.L8
  BOTTOM w0.127: v1(162.4,87.89) 161.86,88.44 R188.2
$11N254: length 36.3
  TOP w0.127: R293.2 v1(241.21,116.47) ; v1(241.72,113.8) 241.72,113.04 240.57,111.9 237.15,111.9 231.05,105.8 231.05,101.1 232.07,100.09 236.13,100.09 237.12,99.09 242.24,99.09 J34.6
  BOTTOM w0.127: v1(241.72,113.8) 241.72,115.96 v1(241.21,116.47)
$12N2: length 2.9
  TOP w0.127: R25.1 104.91,115.03 C300.1 105.12,115.24 U3.10
$12N8: length 12.7
  TOP w0.508: J23.7 108.21,144.32 J23.8
  BOTTOM w0.508: J23.8 105.7,141.05 105.7,135.68 R261.2
$12N9: length 5.3
  TOP w0.508: T2.15 v1(99.7,131.58)
  BOTTOM w0.508: R262.2 99.98,132.69 99.7,132.41 v1(99.7,131.58)
$12N10: length 3.5
  TOP w0.508: v1(106.05,131.54) T2.10
  BOTTOM w0.508: R260.2 105.57,131.54 v1(106.05,131.54)
$12N32: length 8.6
  TOP w0.381: R17.2 118.86,123.15 119.54,123.83 v1(119.92,123.83)
  TOP w0.508: C154.2 118.86,121.18 R17.2 ; R18.2 v1(124.02,123.83)
  BOTTOM w0.508: v1(124.02,123.83) v1(119.92,123.83)
$12N40: length 2.5
  TOP w0.127: R54.1 131.41,118.01 131.41,117.76 130.54,116.89 U4.31
$12N41: length 2.6
  TOP w0.127: R51.1 112.18,116.06 112.18,115.59 111.83,115.24 U3.31
$12N46: length 2
  TOP w0.127: U4.30 131.21,116.39 R53.1
$12N48: length 1.7
  TOP w0.127: R210.1 131.39,115.39 U4.28
$12N50: length 1.9
  TOP w0.127: R76.2 127.52,111.95 126.54,112.93 U4.18
$12N55: length 3.8
  TOP w0.127: U4.15 124.85,114.39 124.57,114.12 124.57,113.37 124.12,112.91 123.58,112.91 R78.2
$12N65: length 1.7
  TOP w0.127: R211.1 112.46,113.74 U3.28
$12N67: length 2
  TOP w0.127: U3.30 112.26,114.74 R52.1
$12N71: length 2.1
  TOP w0.127: U3.16 106.5,110.22 R74.2
$12N73: length 8.9
  TOP w0.381: v1(97.02,122.56) R19.2 97.02,120.17 C160.2
  TOP w0.508: R20.2 v1(102.17,122.56)
  BOTTOM w0.508: v1(97.02,122.56) v1(102.17,122.56)
$12N75: length 2.4
  TOP w0.127: U4.16 124.99,113.89 124.88,113.78 124.88,113.19 R77.2
$12N76: length 3.2
  TOP w0.127: U3.15 106.07,112.74 105.69,112.36 R75.2
$12N77: length 2.7
  TOP w0.127: R73.2 109.12,110.5 108.89,110.73 107.82,110.73 107.62,110.94 U3.18
$12N87: length 9.2
  TOP w0.381: C161.1 108.24,120.89 R22.1 v1(108.78,122.56)
  TOP w0.508: R21.1 v1(103.62,122.57)
  BOTTOM w0.508: v1(108.78,122.56) 103.62,122.56 v1(103.62,122.57)
$12N91: length 14.2
  TOP w0.165: J23.6 106.17,143.39 105.29,142.51 103.95,142.51 103.79,142.34 103.79,141.79 105.09,140.49 105.09,137.3 106.07,136.32 106.07,134.63 106.33,134.38 107.09,134.38 107.32,134.15 T2.9
$12N113: length 14.1
  TOP w0.165: J23.3 103.13,142.87 103.49,142.51 103.49,141.67 104.8,140.37 104.8,137.18 105.78,136.2 105.78,134.63 105.53,134.38 105.06,134.38 104.78,134.1 T2.11
$12N114: length 13.9
  BOTTOM w0.508: R263.1 R260.1 ; R260.1 R262.1 ; R260.1 104.77,134.54 106.63,132.69 R261.1 111.93,132.69 C31.1
$12N115: length 17.2
  TOP w0.165: T2.16 98.43,134.09 98.72,134.38 99.23,134.38 99.47,134.62 99.47,134.91 99.86,135.3 101.55,135.3 103.41,137.17 103.41,140.09 100.46,143.05 100.46,143.75 101.09,144.39 J23.1
$12N116: length 17.1
  TOP w0.165: J23.2 101.64,144.03 101.15,144.03 100.75,143.63 100.75,143.17 103.71,140.21 103.71,137.05 101.67,135.01 99.99,135.01 99.76,134.78 99.76,134.6 99.98,134.38 100.71,134.38 100.97,134.12 T2.14
$12N117: length 7.9
  BOTTOM w0.508: R263.2 104.43,143.27 J23.4 104.14,144.32 J23.5
$12N122: length 7.6
  TOP w0.508: T1.15 v1(121.54,132.6)
  BOTTOM w0.508: v1(121.54,132.6) 123.86,132.6 125.89,134.63 R265.2
$12N123: length 3.7
  TOP w0.508: v1(127.67,131.96) 127.89,132.18 T1.10
  BOTTOM w0.508: R264.2 126.74,132.89 v1(127.67,131.96)
$12N124: length 12.5
  TOP w0.165: J24.6 130.76,143.56 129.11,141.91 129.11,137.59 127.66,136.14 127.66,135.9 127.92,135.65 128.93,135.65 129.16,135.42 T1.9
$12N125: length 12.5
  TOP w0.165: J24.3 128.27,143.1 128.81,142.56 128.81,137.71 127.37,136.26 127.37,135.85 127.17,135.65 126.9,135.65 126.62,135.37 T1.11
$12N126: length 16.6
  TOP w0.165: T1.14 122.81,134.92 122.16,135.57 121.56,135.57 121.22,135.9 119.67,137.45 119.67,140.09 123.14,143.56 J24.2
$12N127: length 16.5
  TOP w0.165: J24.1 126.24,144.03 126.06,143.85 123.02,143.85 119.38,140.21 119.38,137.33 120.69,136.03 120.69,135.78 120.27,135.37 T1.16
$12N128: length 12.2
  TOP w0.508: J24.8 133.35,144.32 J24.7
  BOTTOM w0.508: J24.8 130.85,141.05 130.85,135.47 R267.2
$12N129: length 7.8
  BOTTOM w0.508: J24.5 129.29,144.32 J24.4 129.74,143.1 R266.2
$12N133: length 3.3
  TOP w0.127: U4.10 124.96,116.89 124.04,117.81 C299.1 123.76,117.36 123.71,117.31 R26.1
$12N261: length 8.7
  TOP w0.381: C168.1 130.62,122.69 R24.1
  TOP w0.508: R23.1 v1(125.46,123.83) ; R24.1 130.62,123.42 130.21,123.83 v1(129.83,123.83)
  BOTTOM w0.508: v1(129.83,123.83) v1(125.46,123.83)
$12N279: length 10.6
  BOTTOM w0.508: C32.1 133.92,132.98 R267.1 R264.1 R265.1 128.6,135.1 R266.1
$12N307: length 1.7
  TOP w0.127: U4.12 124.81,115.89 124.37,115.46 R164.2
$12N314: length 2.6
  TOP w0.127: R165.2 105.83,113.27 105.83,114.06 106.02,114.24 U3.12
$13N49: length 1.7
  TOP w0.127: R122.1 202.96,112.28 202.73,112.51 Q7.1
$13N52: length 7.1
  TOP w0.127: J17.1 206.88,114.61 205.78,115.71 Q7.3 203.87,115.83 R216.2
